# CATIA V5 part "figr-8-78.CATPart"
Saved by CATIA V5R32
Part number: Part1
Bounding box of the stored display mesh (mm): x -35 to 35, y -116.369 to 116.369, z 0 to 117.647
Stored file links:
  D:\PROJECTS\Project 2022\CATIA V5 6R 2022\Resources\Part Files\c08_catia_v5_6r2022_prt\figr-8-78.CATPart
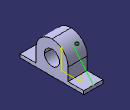
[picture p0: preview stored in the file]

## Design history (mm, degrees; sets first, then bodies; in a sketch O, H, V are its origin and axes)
Body1 (main body)
  Sketch1 on yz-plane, origin (0, 0, 0), H (0, 1, 0), V (0, 0, 1)
    line L1 (0, 0) -> (116.3687, 0)
    point P1 (116.3687, 0)
    line L2 (116.3687, 0) -> (116.3687, 12.5279)
    point P2 (116.3687, 12.5279)
    line L3 (116.3687, 12.5279) -> (58.943, 12.5279)
    point P3 (58.943, 12.5279)
    line L4 (58.943, 12.5279) -> (58.943, 58.7038)
    point P4 (58.943, 58.7038)
    arc A1 centre (0, 58.7038) radius 58.943 from (58.943, 58.7038) to (0, 117.6467) ccw
    point P5 (0, 58.7038)
    point P6 (-58.943, 58.7038)
    line L5 (-58.943, 58.7038) -> (-58.943, 12.5279)
    point P7 (-58.943, 12.5279)
    axis line L6 (0, 0) -> (0, 108.1111)
    point P9 (0, 117.6467)
    point P10 (0, 117.6467)
    point P11 (-58.943, 58.7038)
    arc A2 centre (0, 58.7038) radius 58.943 from (-58.943, 58.7038) to (0, 117.6467) cw
    point P13 (-58.943, 12.5279)
    point P14 (-116.3687, 12.5279)
    line L7 (-116.3687, 12.5279) -> (-58.943, 12.5279)
    point P15 (-116.3687, 0)
    line L8 (-116.3687, 0) -> (-116.3687, 12.5279)
    point P16 (0, 0)
    line L9 (0, 0) -> (-116.3687, 0)
    circle A3 centre (0, 58.7038) radius 27.1825
    horizontal: L1 H, L3 H
    vertical: L2 V, L4 V, L6 V
    tangency: A1 L4, L5 A1
    coincidence: P7 L3, P5 V, L6 P9, P6 P11, O P16, P9 P10, P7 P13
    symmetry: P9 P10 L6, P4 P11 L6, A1 A2 L6, P3 P13 L6, P2 P14 L6, L3 L7 L6, P1 P15 L6, L2 L8 L6, O P16 L6, L1 L9 L6
  Pad1: profile Sketch1, direction (1, 0, 0), length 35, mirrored extent
  Sketch2 on yz-plane, origin (0, 0, 0), H (0, 1, 0), V (0, 0, 1)
    line L1 (116.3687, 12.5279) -> (44.9741, 96.8037)
    point P1 (116.3687, 12.5279)
    point P2 (44.9741, 96.8037)
    reference projected arc E1 centre (0, 58.7038) radius 58.943 from (58.943, 58.7038) to (0, 117.6467) ccw from edge [face of Pad1 | face of Pad1]
    reference projected arc E2 centre (0, 58.7038) radius 58.943 from (58.943, 58.7038) to (0, 117.6467) ccw from edge [face of Pad1 | face of Pad1]
    reference projected point E3 (116.3687, 12.5279) from vertex [face of Pad1 | face of Pad1 | face of Pad1]
    tangency: L1 E1
    coincidence: P2 E2, P1 E3
  Stiffener1: ExtendedProfile Sketch2, ThicknessTop 0, ThicknessValue 15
